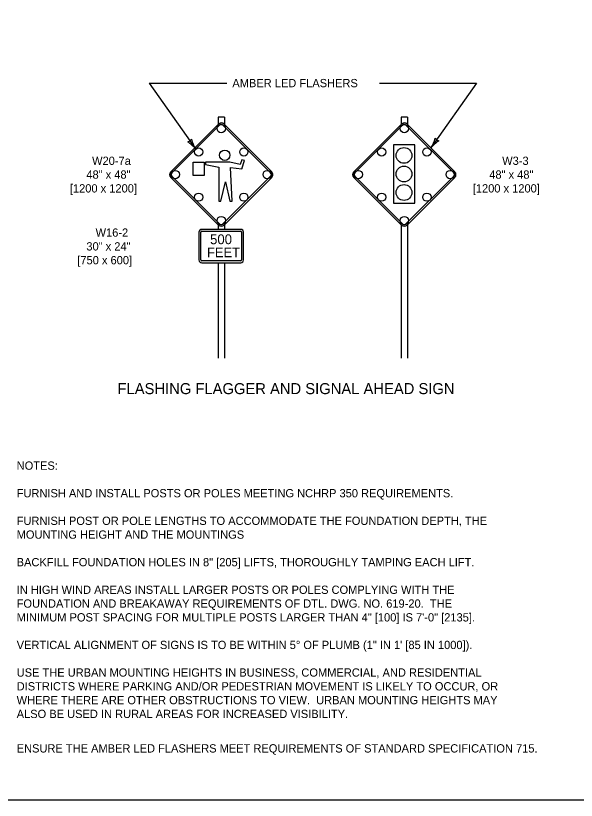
# Model space of a CAD drawing. Extents: x 49991.4 to 50021, y 49987.6 to 50011.4.
# Drawn here: x 50008.62 to 50012.69, y 49987.8 to 49993.49 of the extents above; entities that cross this region are included whole.
import ezdxf

# ---------------------------------------------------------------- set-up
doc = ezdxf.new("R2010")
doc.units = 0
for name, color, linetype in [('Level 1', 7, 'Continuous'), ('Level 2', 7, 'Continuous'), ('Level 25', 7, 'Continuous'), ('Level 3', 7, 'Continuous')]:
    doc.layers.add(name, color=color, linetype=linetype)

msp = doc.modelspace()

# ---------------------------------------------------------------- linework, layer by layer
at = {"layer": 'Level 1'}
for p, q in [((50010.0892, 49992.7526), (50010.0892, 49992.699)), ((50010.1346, 49992.7526), (50010.0892, 49992.7526)), ((50010.1346, 49992.7526), (50010.1346, 49992.699)), ((50011.4162, 49992.7526), (50011.4162, 49992.699)), ((50011.4616, 49992.7526), (50011.4162, 49992.7526)), ((50011.4616, 49992.7526), (50011.4616, 49992.699)), ((50010.0936, 49992.7031), (50009.7457, 49992.3555)), ((50010.0998, 49992.6936), (50009.754, 49992.3474)), ((50010.4701, 49992.3474), (50010.124, 49992.6936)), ((50010.4782, 49992.3555), (50010.1321, 49992.7015)), ((50011.4206, 49992.7031), (50011.0727, 49992.3555)), ((50011.4268, 49992.6936), (50011.081, 49992.3474)), ((50011.7971, 49992.3474), (50011.451, 49992.6936)), ((50011.8052, 49992.3555), (50011.4591, 49992.7015)), ((50009.909, 49992.3285), (50009.909, 49992.4253)), ((50009.909, 49992.4253), (50009.9881, 49992.4253)), ((50009.9881, 49992.4253), (50009.9881, 49992.3285)), ((50010.1751, 49992.4248), (50009.997, 49992.4248)), ((50009.997, 49992.4248), (50009.997, 49992.4087)), ((50010.2499, 49992.4075), (50010.1751, 49992.4248)), ((50010.2608, 49992.4416), (50010.2499, 49992.4075)), ((50010.2796, 49992.4369), (50010.2608, 49992.4416)), ((50010.2624, 49992.3778), (50010.2796, 49992.4369)), ((50009.997, 49992.4087), (50010.0937, 49992.3896)), ((50010.0937, 49992.3896), (50010.0937, 49992.1432)), ((50010.1911, 49992.1432), (50010.1783, 49992.3871)), ((50010.1783, 49992.3871), (50010.2624, 49992.3778)), ((50009.7456, 49992.3152), (50010.0919, 49991.9693)), ((50009.754, 49992.3232), (50010.0998, 49991.9771)), ((50009.9881, 49992.3285), (50009.909, 49992.3285)), ((50010.124, 49991.9771), (50010.4701, 49992.3232)), ((50010.1322, 49991.9693), (50010.4782, 49992.3152)), ((50011.0726, 49992.3152), (50011.4189, 49991.9693)), ((50011.081, 49992.3232), (50011.4268, 49991.9771)), ((50011.451, 49991.9771), (50011.7971, 49992.3232)), ((50011.4592, 49991.9693), (50011.8052, 49992.3152)), ((50010.1094, 49992.1432), (50010.1423, 49992.282)), ((50010.1423, 49992.282), (50010.1753, 49992.1432)), ((50010.0937, 49992.1432), (50010.1094, 49992.1432)), ((50010.1753, 49992.1432), (50010.1911, 49992.1432)), ((50010.0892, 49991.9718), (50010.0892, 49991.938)), ((50010.1346, 49991.9717), (50010.1346, 49991.938)), ((50011.4162, 49991.9718), (50011.4162, 49991.938)), ((50011.4616, 49991.9717), (50011.4616, 49991.938)), ((50011.4162, 49991.938), (50011.4162, 49991.0053)), ((50011.4616, 49991.938), (50011.4616, 49991.0053)), ((50010.0892, 49991.6961), (50010.0892, 49991.0053)), ((50010.1346, 49991.6961), (50010.1346, 49991.0053))]:
    msp.add_line(p, q, dxfattribs=at)
for points in [[(49999.3835, 49998.9992), (50016.7501, 49998.9992), (50016.7501, 49987.7988), (49999.3835, 49987.7988)], [(50011.5145, 49992.1278), (50011.5145, 49992.5512), (50011.36, 49992.5512), (50011.36, 49992.1278)]]:
    msp.add_lwpolyline(points, close=True, dxfattribs=at)
for points in [[(50010.2607, 49992.4414), (50010.2608, 49992.4416)], [(50010.2618, 49992.3779), (50010.2626, 49992.3787)], [(50009.9878, 49992.3285), (50009.9881, 49992.3289)]]:
    msp.add_lwpolyline(points, dxfattribs=at)
for centre, radius in [((50010.1119, 49992.6686), 0.03), ((50011.4389, 49992.6686), 0.03), ((50009.9481, 49992.4993), 0.03), ((50010.2758, 49992.4993), 0.03), ((50011.2751, 49992.4993), 0.03), ((50011.4367, 49992.4742), 0.0572), ((50011.6028, 49992.4993), 0.03), ((50009.779, 49992.3353), 0.03), ((50010.4451, 49992.3353), 0.03), ((50011.106, 49992.3353), 0.03), ((50011.437, 49992.3395), 0.0575), ((50011.7721, 49992.3353), 0.03), ((50011.437, 49992.2051), 0.0575), ((50009.9481, 49992.1714), 0.03), ((50010.2758, 49992.1714), 0.03), ((50011.2751, 49992.1714), 0.03), ((50011.6028, 49992.1714), 0.03), ((50010.1119, 49992.0021), 0.03), ((50011.4389, 49992.0021), 0.03)]:
    msp.add_circle(centre, radius, dxfattribs=at)
for centre, major_axis, start_param, end_param in [((50010.112, 49992.6814), (0, 0.0285), 5.497787, 6.983728), ((50011.439, 49992.6814), (0, 0.0285), 5.497787, 6.983728), ((50010.1119, 49992.6816), (0, 0.0171), 5.497787, 7.068583), ((50011.4389, 49992.6816), (0, 0.0171), 5.497787, 7.068583), ((50009.7658, 49992.3353), (0, 0.0285), 0.785398, 2.356194), ((50009.766, 49992.3353), (0, 0.0171), 0.785398, 2.356194), ((50010.458, 49992.3353), (0, 0.0171), 3.926991, 5.497791), ((50010.4581, 49992.3353), (0, 0.0285), 3.926991, 5.497791), ((50011.0928, 49992.3353), (0, 0.0285), 0.785398, 2.356194), ((50011.093, 49992.3353), (0, 0.0171), 0.785398, 2.356194), ((50011.785, 49992.3353), (0, 0.0171), 3.926991, 5.497791), ((50011.7851, 49992.3353), (0, 0.0285), 3.926991, 5.497791), ((50010.112, 49991.9894), (0, -0.0285), 5.497787, 7.068576), ((50010.1119, 49991.9891), (0, -0.0171), 5.497787, 7.068576), ((50011.439, 49991.9894), (0, -0.0285), 5.497787, 7.068576), ((50011.4389, 49991.9891), (0, -0.0171), 5.497787, 7.068576)]:
    msp.add_ellipse(centre, major_axis=major_axis, ratio=0.999981, start_param=start_param, end_param=end_param, dxfattribs=at)
msp.add_ellipse((50010.1373, 49992.4753), major_axis=(0, 0.038), ratio=0.999981, dxfattribs=at)
at = {"layer": 'Level 25'}
for p, q in [((50009.9506, 49991.9178), (50009.9506, 49991.7162)), ((50009.9641, 49991.7162), (50009.9641, 49991.9178)), ((50010.2531, 49991.938), (50009.9708, 49991.938)), ((50009.9708, 49991.9246), (50010.2531, 49991.9246)), ((50010.2598, 49991.9178), (50010.2598, 49991.7162)), ((50010.2732, 49991.7162), (50010.2732, 49991.9178)), ((50010.2531, 49991.7095), (50009.9708, 49991.7095)), ((50009.9708, 49991.6961), (50010.2531, 49991.6961))]:
    msp.add_line(p, q, dxfattribs=at)
for centre, radius, start, end in [((50009.9708, 49991.9178), 0.0202, 90, 180), ((50009.9708, 49991.9178), 0.00672, 90, 180), ((50010.2531, 49991.9178), 0.0202, 0, 90), ((50010.2531, 49991.9178), 0.00672, 0, 90), ((50009.9708, 49991.7162), 0.0202, 180, 270), ((50009.9708, 49991.7162), 0.00672, 180, 270), ((50010.2531, 49991.7162), 0.00672, 270, 360), ((50010.2531, 49991.7162), 0.0202, 270, 360)]:
    msp.add_arc(centre, radius, start, end, dxfattribs=at)
at = {"layer": 'Level 3'}
for p, q in [((50009.5899, 49992.9986), (50009.9269, 49992.5205)), ((50009.5899, 49992.9986), (50010.1524, 49992.9986)), ((50011.2586, 49992.9986), (50011.9635, 49992.9986)), ((50011.9635, 49992.9986), (50011.6321, 49992.5285))]:
    msp.add_line(p, q, dxfattribs=at)
for centre, radius, start, end in [((50009.8516, 49992.6243), 0.0548, 288.1145, 323.8369), ((50010.112, 49992.6436), 0.2223, 193.4317, 213.6152), ((50011.447, 49992.6516), 0.2223, 326.3848, 346.5683), ((50011.7075, 49992.6322), 0.0548, 216.1631, 251.8855), ((50009.7453, 49992.3745), 0.233, 38.803, 58.0529), ((50011.8137, 49992.3825), 0.233, 121.9471, 141.197)]:
    msp.add_arc(centre, radius, start, end, dxfattribs=at)

# ---------------------------------------------------------------- texts
at = {"layer": 'Level 2'}
for s, height, p in [('AMBER LED FLASHERS', 0.06, (50010.1924, 49992.9686)), ('W20-7a', 0.06, (50009.1756, 49992.4053)), ('W3-3', 0.06, (50012.1487, 49992.4053)), ('48" x 48"', 0.06, (50009.1342, 49992.3053)), ('48" x 48"', 0.06, (50012.0549, 49992.3053)), ('[1200 x 1200]', 0.06, (50009.0147, 49992.2053)), ('[1200 x 1200]', 0.06, (50011.9355, 49992.2053)), ('W16-2', 0.06, (50009.2011, 49991.8848)), ('30" x 24"', 0.06, (50009.1342, 49991.7848)), ('[750 x 600]', 0.06, (50009.0686, 49991.6848)), ('FLASHING FLAGGER AND SIGNAL AHEAD SIGN', 0.08, (50009.36, 49990.7435)), ('NOTES:', 0.06, (50008.6289, 49990.1953)), ('FURNISH AND INSTALL POSTS OR POLES MEETING NCHRP 350 REQUIREMENTS.', 0.06, (50008.6289, 49989.9953)), ('FURNISH POST OR POLE LENGTHS TO ACCOMMODATE THE FOUNDATION DEPTH, THE', 0.06, (50008.6289, 49989.7953)), ('MOUNTING HEIGHT AND THE MOUNTINGS', 0.06, (50008.6289, 49989.6953)), ('BACKFILL FOUNDATION HOLES IN 8" [205] LIFTS, THOROUGHLY TAMPING EACH LIFT.', 0.06, (50008.6289, 49989.4953)), ('IN HIGH WIND AREAS INSTALL LARGER POSTS OR POLES COMPLYING WITH THE', 0.06, (50008.6289, 49989.2953)), ('FOUNDATION AND BREAKAWAY REQUIREMENTS OF DTL. DWG. NO. 619-20.  THE ', 0.06, (50008.6289, 49989.1953)), ('MINIMUM POST SPACING FOR MULTIPLE POSTS LARGER THAN 4" [100] IS 7\'-0" [2135].', 0.06, (50008.6289, 49989.0953)), ('VERTICAL ALIGNMENT OF SIGNS IS TO BE WITHIN 5° OF PLUMB (1" IN 1\' [85 IN 1000]).', 0.06, (50008.6289, 49988.8953)), ('USE THE URBAN MOUNTING HEIGHTS IN BUSINESS, COMMERCIAL, AND RESIDENTIAL ', 0.06, (50008.6289, 49988.6953)), ('DISTRICTS WHERE PARKING AND/OR PEDESTRIAN MOVEMENT IS LIKELY TO OCCUR, OR ', 0.06, (50008.6289, 49988.5953)), ('WHERE THERE ARE OTHER OBSTRUCTIONS TO VIEW.  URBAN MOUNTING HEIGHTS MAY ', 0.06, (50008.6289, 49988.4953)), ('ALSO BE USED IN RURAL AREAS FOR INCREASED VISIBILITY.', 0.06, (50008.6289, 49988.3953)), ('ENSURE THE AMBER LED FLASHERS MEET REQUIREMENTS OF STANDARD SPECIFICATION 715.', 0.06, (50008.6289, 49988.1453))]:
    msp.add_text(s, height=height, dxfattribs=at).set_placement(p)
at = {"layer": 'Level 25'}
for s, height, p in [('500', 0.07124, (50010.031, 49991.8305)), ('FEET', 0.06989, (50010.0087, 49991.7364))]:
    msp.add_text(s, height=height, dxfattribs=at).set_placement(p)

doc.saveas('drawing.dxf')
